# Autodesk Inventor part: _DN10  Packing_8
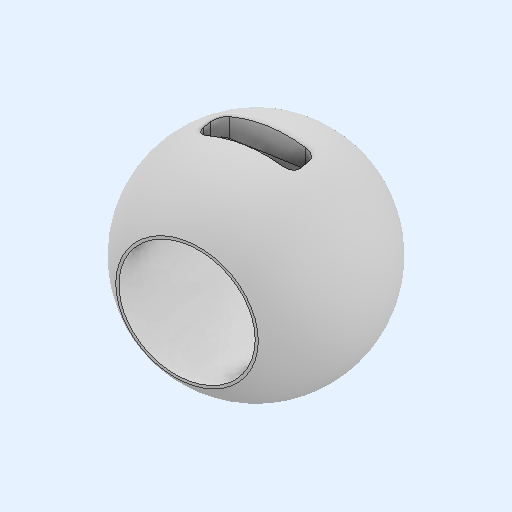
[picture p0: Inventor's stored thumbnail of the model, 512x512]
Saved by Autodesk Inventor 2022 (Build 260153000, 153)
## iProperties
Created: 2021-12
Part Number: _DN10  Packing_8
Material: Generico
Document SubType Name: Modeling
Designer: admin
Density: 1 g/cm^3
Appearance: Default
Author: admin
Revision Number: NONE
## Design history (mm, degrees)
feature "_DN10  Packing"
node "Solido1"
